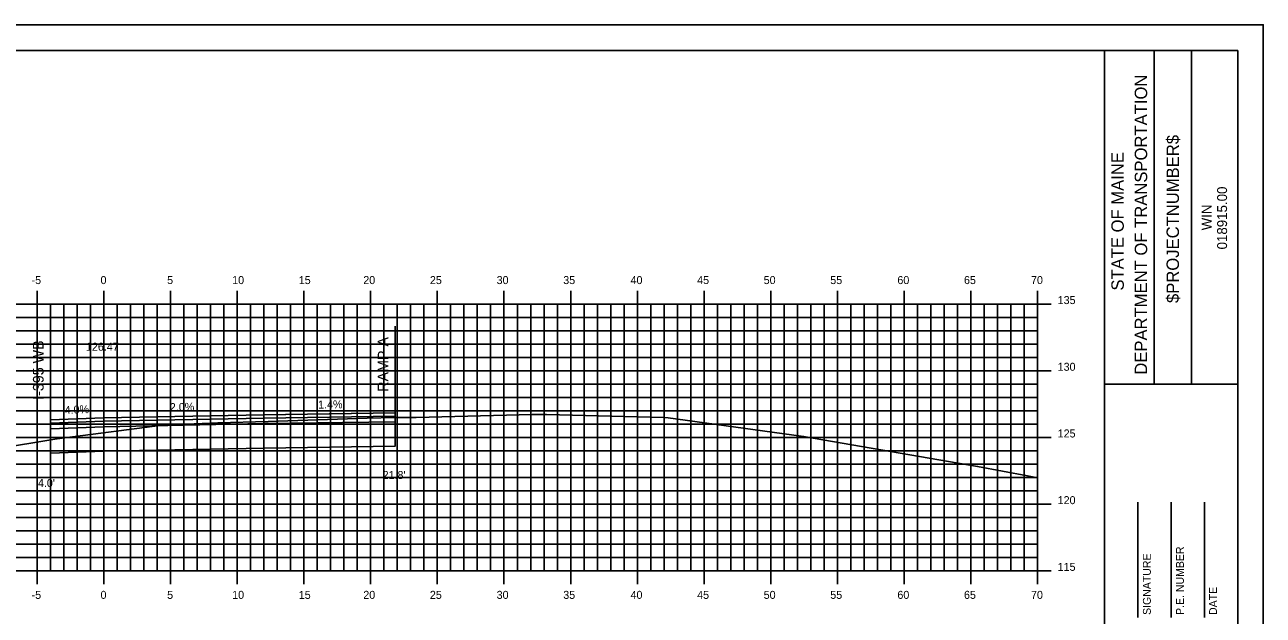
# Model space of a CAD drawing. Extents: x 851738 to 851910, y 365624 to 365734.
# Drawn here: x 851815.6 to 851908.4, y 365689.7 to 365734 of the extents above; entities that cross this region are included whole.
import ezdxf

# ---------------------------------------------------------------- set-up
doc = ezdxf.new("R2010")
doc.units = 0
for name, color, linetype in [('ANNOTATION', 7, 'Continuous'), ('BORDER', 7, 'Continuous'), ('D_Roadway_Centerline', 7, 'Continuous'), ('D_Roadway_Centerline_Text', 7, 'Continuous'), ('D_Roadway_Edge_Shoulder', 7, 'Continuous'), ('D_Roadway_Edge_TW', 7, 'Continuous'), ('D_Roadway_FinishedGrade', 7, 'Continuous'), ('D_Roadway_Pavement', 7, 'Continuous'), ('D_Roadway_SubGrade', 7, 'Continuous'), ('D_Text_Standard', 7, 'Continuous'), ('H_V ANNOTATION', 7, 'Continuous'), ('M_Roadway_Centerline', 7, 'Continuous'), ('MAJOR', 7, 'Continuous'), ('MINOR', 7, 'Continuous'), ('PLOT BOUNDARY', 7, 'Continuous'), ('S_Roadway_Centerline', 7, 'Continuous')]:
    doc.layers.add(name, color=color, linetype=linetype)

msp = doc.modelspace()

# ---------------------------------------------------------------- linework, layer by layer
at = {"layer": 'BORDER'}
for p, q in [((851896.522, 365627.027), (851896.522, 365732.027)), ((851900.251, 365707.024), (851900.251, 365732.024)), ((851903.046, 365707.024), (851903.046, 365732.024)), ((851896.523, 365707.021), (851906.522, 365707.021)), ((851899.022, 365689.53), (851899.022, 365698.177)), ((851901.522, 365689.53), (851901.522, 365698.177)), ((851904.022, 365689.53), (851904.022, 365698.177))]:
    msp.add_line(p, q, dxfattribs=at)
msp.add_lwpolyline([(851746.522, 365627.027), (851906.522, 365627.027), (851906.522, 365732.027), (851746.522, 365732.027)], close=True, dxfattribs=at)
at = {"layer": 'D_Roadway_Centerline'}
msp.add_lwpolyline([(851817.522, 365704.338), (851821.521, 365704.498), (851821.522, 365704.498), (851833.518, 365704.735), (851833.522, 365704.735), (851838.426, 365704.804), (851843.364, 365704.873)], dxfattribs=at)
at = {"layer": 'D_Roadway_Edge_Shoulder'}
msp.add_lwpolyline([(851821.522, 365704.498), (851817.522, 365704.338), (851817.522, 365704.088), (851821.522, 365704.248)], close=True, dxfattribs=at)
at = {"layer": 'D_Roadway_Edge_TW'}
for points in [[(851821.522, 365704.498), (851833.522, 365704.735), (851833.522, 365704.485), (851821.522, 365704.248)], [(851833.522, 365704.735), (851843.363, 365704.873), (851843.363, 365704.623), (851833.522, 365704.485)]]:
    msp.add_lwpolyline(points, close=True, dxfattribs=at)
at = {"layer": 'D_Roadway_FinishedGrade'}
for p, q in [((851821.522, 365704.498), (851821.522, 365704.248)), ((851833.522, 365704.735), (851833.522, 365704.485)), ((851843.363, 365704.873), (851843.363, 365704.623)), ((851817.522, 365704.338), (851817.522, 365704.088))]:
    msp.add_line(p, q, dxfattribs=at)
at = {"layer": 'D_Roadway_Pavement'}
for points in [[(851821.522, 365704.248), (851833.522, 365704.485), (851833.522, 365704.069), (851821.522, 365703.831)], [(851833.522, 365704.485), (851843.363, 365704.623), (851843.363, 365704.206), (851833.522, 365704.069)], [(851821.522, 365704.248), (851817.522, 365704.088), (851817.522, 365703.671), (851821.522, 365703.831)]]:
    msp.add_lwpolyline(points, close=True, dxfattribs=at)
at = {"layer": 'D_Roadway_SubGrade'}
for p, q in [((851843.363, 365711.37), (851843.363, 365702.373)), ((851817.522, 365710.835), (851817.522, 365701.838))]:
    msp.add_line(p, q, dxfattribs=at)
for points in [[(851821.522, 365703.831), (851817.522, 365703.671), (851817.522, 365704.171), (851817.522, 365704.338), (851817.522, 365701.838), (851821.522, 365701.998)], [(851821.522, 365703.831), (851833.522, 365704.069), (851833.522, 365702.235), (851821.522, 365701.998)], [(851833.522, 365704.069), (851843.363, 365704.206), (851843.363, 365702.373), (851833.522, 365702.235)]]:
    msp.add_lwpolyline(points, close=True, dxfattribs=at)
at = {"layer": 'MAJOR'}
for p, q in [((851816.522, 365714.029), (851816.522, 365713.027)), ((851821.522, 365714.029), (851821.522, 365713.027)), ((851826.522, 365714.029), (851826.522, 365713.027)), ((851831.522, 365714.029), (851831.522, 365713.027)), ((851836.522, 365714.029), (851836.522, 365713.027)), ((851841.522, 365714.029), (851841.522, 365713.027)), ((851846.522, 365714.029), (851846.522, 365713.027)), ((851851.522, 365714.029), (851851.522, 365713.027)), ((851856.522, 365714.029), (851856.522, 365713.027)), ((851861.522, 365714.029), (851861.522, 365713.027)), ((851866.522, 365714.029), (851866.522, 365713.027)), ((851871.522, 365714.029), (851871.522, 365713.027)), ((851876.522, 365714.029), (851876.522, 365713.027)), ((851881.522, 365714.029), (851881.522, 365713.027)), ((851886.522, 365714.029), (851886.522, 365713.027)), ((851891.522, 365714.029), (851891.522, 365713.027)), ((851751.522, 365713.027), (851891.522, 365713.027)), ((851751.522, 365713.027), (851891.522, 365713.027)), ((851816.522, 365693.027), (851816.522, 365713.027)), ((851821.522, 365693.027), (851821.522, 365713.027)), ((851826.522, 365693.027), (851826.522, 365713.027)), ((851831.522, 365693.027), (851831.522, 365713.027)), ((851836.522, 365693.027), (851836.522, 365713.027)), ((851841.522, 365693.027), (851841.522, 365713.027)), ((851846.522, 365693.027), (851846.522, 365713.027)), ((851851.522, 365693.027), (851851.522, 365713.027)), ((851856.522, 365693.027), (851856.522, 365713.027)), ((851861.522, 365693.027), (851861.522, 365713.027)), ((851866.522, 365693.027), (851866.522, 365713.027)), ((851871.522, 365693.027), (851871.522, 365713.027)), ((851876.522, 365693.027), (851876.522, 365713.027)), ((851881.522, 365693.027), (851881.522, 365713.027)), ((851886.522, 365693.027), (851886.522, 365713.027)), ((851892.524, 365713.027), (851890.52, 365713.027)), ((851891.522, 365693.027), (851891.522, 365713.027)), ((851891.522, 365693.027), (851891.522, 365713.027)), ((851751.522, 365708.027), (851891.522, 365708.027)), ((851892.524, 365708.027), (851890.52, 365708.027)), ((851751.522, 365703.027), (851891.522, 365703.027)), ((851892.524, 365703.027), (851890.52, 365703.027)), ((851751.522, 365698.027), (851891.522, 365698.027)), ((851892.524, 365698.027), (851890.52, 365698.027)), ((851751.522, 365693.027), (851891.522, 365693.027)), ((851751.522, 365693.027), (851891.522, 365693.027)), ((851816.522, 365692.025), (851816.522, 365693.027)), ((851821.522, 365692.025), (851821.522, 365693.027)), ((851826.522, 365692.025), (851826.522, 365693.027)), ((851831.522, 365692.025), (851831.522, 365693.027)), ((851836.522, 365692.025), (851836.522, 365693.027)), ((851841.522, 365692.025), (851841.522, 365693.027)), ((851846.522, 365692.025), (851846.522, 365693.027)), ((851851.522, 365692.025), (851851.522, 365693.027)), ((851856.522, 365692.025), (851856.522, 365693.027)), ((851861.522, 365692.025), (851861.522, 365693.027)), ((851866.522, 365692.025), (851866.522, 365693.027)), ((851871.522, 365692.025), (851871.522, 365693.027)), ((851876.522, 365692.025), (851876.522, 365693.027)), ((851881.522, 365692.025), (851881.522, 365693.027)), ((851886.522, 365692.025), (851886.522, 365693.027)), ((851892.524, 365693.027), (851890.52, 365693.027)), ((851891.522, 365692.025), (851891.522, 365693.027))]:
    msp.add_line(p, q, dxfattribs=at)
at = {"layer": 'MINOR'}
for p, q in [((851817.522, 365693.027), (851817.522, 365713.027)), ((851818.522, 365693.027), (851818.522, 365713.027)), ((851819.522, 365693.027), (851819.522, 365713.027)), ((851820.522, 365693.027), (851820.522, 365713.027)), ((851822.522, 365693.027), (851822.522, 365713.027)), ((851823.522, 365693.027), (851823.522, 365713.027)), ((851824.522, 365693.027), (851824.522, 365713.027)), ((851825.522, 365693.027), (851825.522, 365713.027)), ((851827.522, 365693.027), (851827.522, 365713.027)), ((851828.522, 365693.027), (851828.522, 365713.027)), ((851829.522, 365693.027), (851829.522, 365713.027)), ((851830.522, 365693.027), (851830.522, 365713.027)), ((851832.522, 365693.027), (851832.522, 365713.027)), ((851833.522, 365693.027), (851833.522, 365713.027)), ((851834.522, 365693.027), (851834.522, 365713.027)), ((851835.522, 365693.027), (851835.522, 365713.027)), ((851837.522, 365693.027), (851837.522, 365713.027)), ((851838.522, 365693.027), (851838.522, 365713.027)), ((851839.522, 365693.027), (851839.522, 365713.027)), ((851840.522, 365693.027), (851840.522, 365713.027)), ((851842.522, 365693.027), (851842.522, 365713.027)), ((851843.522, 365693.027), (851843.522, 365713.027)), ((851844.522, 365693.027), (851844.522, 365713.027)), ((851845.522, 365693.027), (851845.522, 365713.027)), ((851847.522, 365693.027), (851847.522, 365713.027)), ((851848.522, 365693.027), (851848.522, 365713.027)), ((851849.522, 365693.027), (851849.522, 365713.027)), ((851850.522, 365693.027), (851850.522, 365713.027)), ((851852.522, 365693.027), (851852.522, 365713.027)), ((851853.522, 365693.027), (851853.522, 365713.027)), ((851854.522, 365693.027), (851854.522, 365713.027)), ((851855.522, 365693.027), (851855.522, 365713.027)), ((851857.522, 365693.027), (851857.522, 365713.027)), ((851858.522, 365693.027), (851858.522, 365713.027)), ((851859.522, 365693.027), (851859.522, 365713.027)), ((851860.522, 365693.027), (851860.522, 365713.027)), ((851862.522, 365693.027), (851862.522, 365713.027)), ((851863.522, 365693.027), (851863.522, 365713.027)), ((851864.522, 365693.027), (851864.522, 365713.027)), ((851865.522, 365693.027), (851865.522, 365713.027)), ((851867.522, 365693.027), (851867.522, 365713.027)), ((851868.522, 365693.027), (851868.522, 365713.027)), ((851869.522, 365693.027), (851869.522, 365713.027)), ((851870.522, 365693.027), (851870.522, 365713.027)), ((851872.522, 365693.027), (851872.522, 365713.027)), ((851873.522, 365693.027), (851873.522, 365713.027)), ((851874.522, 365693.027), (851874.522, 365713.027)), ((851875.522, 365693.027), (851875.522, 365713.027)), ((851877.522, 365693.027), (851877.522, 365713.027)), ((851878.522, 365693.027), (851878.522, 365713.027)), ((851879.522, 365693.027), (851879.522, 365713.027)), ((851880.522, 365693.027), (851880.522, 365713.027)), ((851882.522, 365693.027), (851882.522, 365713.027)), ((851883.522, 365693.027), (851883.522, 365713.027)), ((851884.522, 365693.027), (851884.522, 365713.027)), ((851885.522, 365693.027), (851885.522, 365713.027)), ((851887.522, 365693.027), (851887.522, 365713.027)), ((851888.522, 365693.027), (851888.522, 365713.027)), ((851889.522, 365693.027), (851889.522, 365713.027)), ((851890.522, 365693.027), (851890.522, 365713.027)), ((851751.522, 365712.027), (851891.522, 365712.027)), ((851891.522, 365712.027), (851890.52, 365712.027)), ((851751.522, 365711.027), (851891.522, 365711.027)), ((851891.522, 365711.027), (851890.52, 365711.027)), ((851751.522, 365710.027), (851891.522, 365710.027)), ((851891.522, 365710.027), (851890.52, 365710.027)), ((851751.522, 365709.027), (851891.522, 365709.027)), ((851891.522, 365709.027), (851890.52, 365709.027)), ((851751.522, 365707.027), (851891.522, 365707.027)), ((851891.522, 365707.027), (851890.52, 365707.027)), ((851751.522, 365706.027), (851891.522, 365706.027)), ((851891.522, 365706.027), (851890.52, 365706.027)), ((851751.522, 365705.027), (851891.522, 365705.027)), ((851891.522, 365705.027), (851890.52, 365705.027)), ((851751.522, 365704.027), (851891.522, 365704.027)), ((851891.522, 365704.027), (851890.52, 365704.027)), ((851751.522, 365702.027), (851891.522, 365702.027)), ((851891.522, 365702.027), (851890.52, 365702.027)), ((851751.522, 365701.027), (851891.522, 365701.027)), ((851891.522, 365701.027), (851890.52, 365701.027)), ((851751.522, 365700.027), (851891.522, 365700.027)), ((851891.522, 365700.027), (851890.52, 365700.027)), ((851751.522, 365699.027), (851891.522, 365699.027)), ((851891.522, 365699.027), (851890.52, 365699.027)), ((851751.522, 365697.027), (851891.522, 365697.027)), ((851891.522, 365697.027), (851890.52, 365697.027)), ((851751.522, 365696.027), (851891.522, 365696.027)), ((851891.522, 365696.027), (851890.52, 365696.027)), ((851751.522, 365695.027), (851891.522, 365695.027)), ((851891.522, 365695.027), (851890.52, 365695.027)), ((851751.522, 365694.027), (851891.522, 365694.027)), ((851891.522, 365694.027), (851890.52, 365694.027))]:
    msp.add_line(p, q, dxfattribs=at)
at = {"layer": 'PLOT BOUNDARY'}
msp.add_lwpolyline([(851738.429, 365623.968), (851908.429, 365623.968), (851908.429, 365733.968), (851738.429, 365733.968)], close=True, dxfattribs=at)
at = {"layer": 'S_Roadway_Centerline'}
msp.add_lwpolyline([(851813.468, 365702.176), (851817.844, 365702.898), (851818.604, 365703), (851825.922, 365703.941), (851830.069, 365704.116), (851833.857, 365704.218), (851841.276, 365704.462), (851843.333, 365704.527), (851844.942, 365704.514), (851853.638, 365704.743), (851854.709, 365704.76), (851863.512, 365704.513), (851863.828, 365704.497), (851865.109, 365704.33), (851873.979, 365703.107), (851887.013, 365700.855), (851890.748, 365700.158), (851891.522, 365700.006)], dxfattribs=at)

# ---------------------------------------------------------------- texts
at = {"layer": 'ANNOTATION'}
for s, height, rotation, p in [('I-395 WB', 0.8, 90, (851817.015, 365705.845)), ('RAMP A', 0.8, 90, (851842.857, 365706.454)), ('-4.0%', 0.6, 2.29042, (851818.337, 365704.771)), ('2.0%', 0.6, 1.13143, (851826.484, 365704.996)), ('1.4%', 0.6, 0.80335, (851837.594, 365705.192))]:
    msp.add_text(s, height=height, rotation=rotation, dxfattribs=at).set_placement(p)
at = {"layer": 'BORDER'}
for s, height, p in [('DEPARTMENT OF TRANSPORTATION', 0.93176, (851899.729, 365707.733)), ('$PROJECTNUMBER$', 0.93176, (851902.114, 365713.106)), ('STATE OF MAINE', 0.93176, (851897.978, 365714.039)), ('018915.00', 0.7453, (851905.718, 365717.125)), ('WIN', 0.7453, (851904.559, 365718.557)), ('SIGNATURE', 0.5906, (851900.003, 365689.722)), ('P.E. NUMBER', 0.59055, (851902.483, 365689.722)), ('DATE', 0.5906, (851904.963, 365689.722))]:
    msp.add_text(s, height=height, rotation=90, dxfattribs=at).set_placement(p)
at = {"layer": 'D_Roadway_Centerline'}
for s, p in [('C', (851821.517, 365704.498)), ('L', (851821.522, 365704.49))]:
    msp.add_text(s, height=0.0146, dxfattribs=at).set_placement(p)
at = {"layer": 'D_Roadway_Centerline_Text'}
msp.add_text('126.47', height=0.6, dxfattribs=at).set_placement((851820.19, 365709.53))
at = {"layer": 'D_Text_Standard'}
for s, p in [("4.0'", (851816.588, 365699.312)), ("21.8'", (851842.425, 365699.911))]:
    msp.add_text(s, height=0.6, dxfattribs=at).set_placement(p)
at = {"layer": 'H_V ANNOTATION'}
for s, p in [('-5', (851816.113, 365714.527)), ('0', (851821.281, 365714.527)), ('5', (851826.273, 365714.527)), ('10', (851831.148, 365714.527)), ('15', (851836.14, 365714.527)), ('20', (851840.976, 365714.527)), ('25', (851845.968, 365714.527)), ('30', (851850.971, 365714.527)), ('35', (851855.963, 365714.527)), ('40', (851861.008, 365714.527)), ('45', (851866, 365714.527)), ('50', (851870.987, 365714.527)), ('55', (851875.979, 365714.527)), ('60', (851881.008, 365714.527)), ('65', (851886, 365714.527)), ('70', (851891.024, 365714.527)), ('135', (851893.022, 365713.027)), ('130', (851893.022, 365708.027)), ('125', (851893.022, 365703.027)), ('120', (851893.022, 365698.027)), ('115', (851893.022, 365693.027)), ('-5', (851816.113, 365690.927)), ('0', (851821.281, 365690.927)), ('5', (851826.273, 365690.927)), ('10', (851831.148, 365690.927)), ('15', (851836.14, 365690.927)), ('20', (851840.976, 365690.927)), ('25', (851845.968, 365690.927)), ('30', (851850.971, 365690.927)), ('35', (851855.963, 365690.927)), ('40', (851861.008, 365690.927)), ('45', (851866, 365690.927)), ('50', (851870.987, 365690.927)), ('55', (851875.979, 365690.927)), ('60', (851881.008, 365690.927)), ('65', (851886, 365690.927)), ('70', (851891.024, 365690.927))]:
    msp.add_text(s, height=0.6, dxfattribs=at).set_placement(p)
at = {"layer": 'M_Roadway_Centerline'}
for s, p in [('C', (851843.328, 365704.527)), ('L', (851843.333, 365704.52))]:
    msp.add_text(s, height=0.0146, dxfattribs=at).set_placement(p)

doc.saveas('drawing.dxf')
